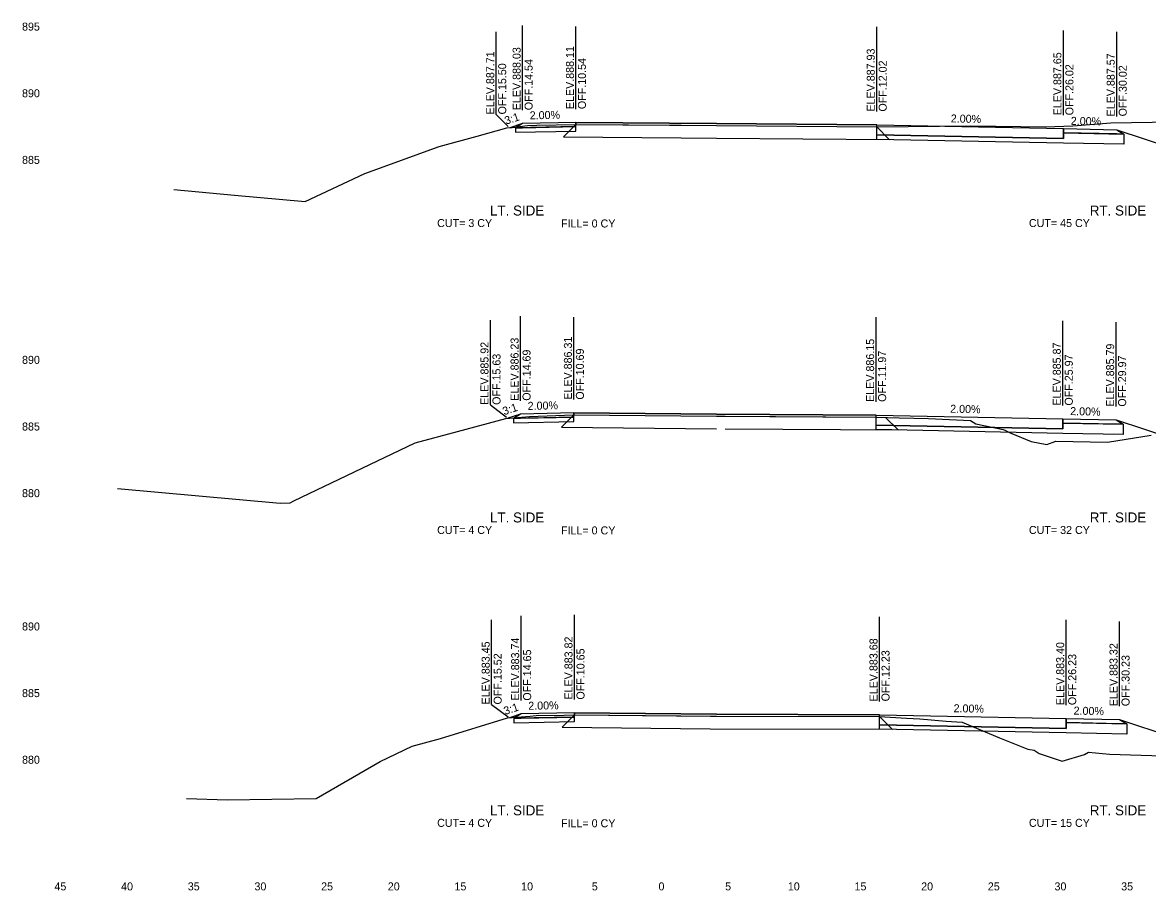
# Model space of a CAD drawing. Extents: x -4 to 359, y 0 to 1436.
# Drawn here: x -3.9 to 80.5, y 1200.5 to 1265.6 of the extents above; entities that cross this region are included whole.
import ezdxf

# ---------------------------------------------------------------- set-up
doc = ezdxf.new("R2010")
doc.units = 0
for name, color, linetype in [('XS-Existing subsurface-pavement', 7, 'Continuous'), ('XS-Existing surface-ground', 7, 'Continuous'), ('XS-Proposed Finish Grade', 7, 'Continuous'), ('XS-Proposed subsurface-aggregate layer 1', 7, 'Continuous'), ('XS-Proposed surface-ground', 7, 'Continuous'), ('XS-Proposed surface-pavement', 7, 'Continuous'), ('XS-Proposed surface-shoulder', 7, 'Continuous'), ('XS-Text-ditch slope', 7, 'Continuous'), ('XS-Text-earthwork labels', 7, 'Continuous'), ('XS-Text-elevation', 7, 'Continuous'), ('XS-Text-offset label', 7, 'Continuous'), ('XS-Text-pavement elevation', 7, 'Continuous'), ('XS-Text-pavement slope', 7, 'Continuous'), ('XS-Text-profile report', 7, 'Continuous'), ('XS-Text-shoulder elevation', 7, 'Continuous'), ('XS-Text-shoulder slope', 7, 'Continuous'), ('XS-Text-tie elevation', 7, 'Continuous'), ('XS-Text-tie offset', 7, 'Continuous')]:
    doc.layers.add(name, color=color, linetype=linetype)

msp = doc.modelspace()

# ---------------------------------------------------------------- linework, layer by layer
at = {"layer": 'XS-Existing subsurface-pavement'}
for p, q in [((37.593, 1257.928), (36.664, 1256.999)), ((60.149, 1257.744), (61.094, 1256.799)), ((36.664, 1256.999), (45.485, 1256.92)), ((45.486, 1256.92), (48.123, 1256.9)), ((48.123, 1256.9), (61.094, 1256.799)), ((37.439, 1236.132), (36.51, 1235.203)), ((36.51, 1235.203), (48.122, 1235.1)), ((60.819, 1235.95), (61.748, 1235.02)), ((48.789, 1235.094), (61.748, 1235.02)), ((37.484, 1213.633), (36.556, 1212.705)), ((60.358, 1213.497), (61.298, 1212.557)), ((36.556, 1212.705), (47.664, 1212.595)), ((47.664, 1212.595), (61.298, 1212.557))]:
    msp.add_line(p, q, dxfattribs=at)
at = {"layer": 'XS-Existing surface-ground'}
for p, q in [((74.849, 1257.813), (77.702, 1258.049)), ((77.702, 1258.049), (82.853, 1258.131)), ((30.192, 1257.053), (32.409, 1257.659)), ((32.409, 1257.659), (32.802, 1257.689)), ((32.802, 1257.689), (33.958, 1257.851)), ((33.958, 1257.851), (34.654, 1257.876)), ((34.654, 1257.876), (37.593, 1257.928)), ((37.593, 1257.928), (45.493, 1257.858)), ((45.493, 1257.858), (48.13, 1257.837)), ((48.13, 1257.837), (60.149, 1257.744)), ((60.149, 1257.744), (67.209, 1257.831)), ((67.209, 1257.831), (72.844, 1257.735)), ((72.844, 1257.735), (74.849, 1257.813)), ((21.756, 1254.233), (27.325, 1256.279)), ((27.325, 1256.279), (30.192, 1257.053)), ((17.28, 1252.137), (21.756, 1254.233)), ((7.427, 1253.042), (11.986, 1252.627)), ((11.986, 1252.627), (17.28, 1252.137)), ((33.843, 1235.987), (34.116, 1236.025)), ((34.116, 1236.025), (36.745, 1236.12)), ((36.745, 1236.12), (37.439, 1236.132)), ((37.439, 1236.132), (48.13, 1236.037)), ((48.13, 1236.037), (48.795, 1236.031)), ((48.795, 1236.031), (60.104, 1235.967)), ((28.713, 1234.885), (32.326, 1235.874)), ((32.326, 1235.874), (33.843, 1235.987)), ((60.104, 1235.967), (61.825, 1235.925)), ((61.825, 1235.925), (64.042, 1235.854)), ((64.042, 1235.854), (67.193, 1235.716)), ((67.193, 1235.716), (67.582, 1235.464)), ((67.582, 1235.464), (69.624, 1235.051)), ((25.543, 1234.029), (28.713, 1234.885)), ((69.624, 1235.051), (69.749, 1234.993)), ((69.749, 1234.993), (70.164, 1234.789)), ((70.164, 1234.789), (71.732, 1234.132)), ((77.453, 1234.084), (80.726, 1234.624)), ((16.432, 1229.69), (25.543, 1234.029)), ((71.732, 1234.132), (72.912, 1233.905)), ((72.912, 1233.905), (73.576, 1234.175)), ((73.576, 1234.175), (77.453, 1234.084)), ((3.218, 1230.621), (15.416, 1229.525)), ((15.416, 1229.525), (16.167, 1229.536)), ((16.167, 1229.536), (16.432, 1229.69)), ((27.433, 1211.847), (32.448, 1213.397)), ((32.448, 1213.397), (34.151, 1213.545)), ((34.151, 1213.545), (34.618, 1213.58)), ((34.618, 1213.58), (36.706, 1213.605)), ((36.706, 1213.605), (37.484, 1213.633)), ((37.484, 1213.633), (47.673, 1213.532)), ((47.673, 1213.532), (48.13, 1213.531)), ((48.13, 1213.531), (60.358, 1213.497)), ((60.358, 1213.497), (62.384, 1213.393)), ((62.384, 1213.393), (63.387, 1213.324)), ((63.387, 1213.324), (65.358, 1213.168)), ((65.358, 1213.168), (66.55, 1213.08)), ((66.55, 1213.08), (69.35, 1211.912)), ((25.316, 1211.275), (27.433, 1211.847)), ((69.35, 1211.912), (71.484, 1211.069)), ((22.912, 1210.131), (25.316, 1211.275)), ((71.484, 1211.069), (71.951, 1210.974)), ((71.951, 1210.974), (72.329, 1210.742)), ((72.329, 1210.742), (74.047, 1210.151)), ((75.721, 1210.667), (76.035, 1210.827)), ((76.035, 1210.827), (77.615, 1210.676)), ((18.117, 1207.346), (22.912, 1210.131)), ((74.047, 1210.151), (75.721, 1210.667)), ((77.615, 1210.676), (92.244, 1210.228)), ((8.376, 1207.348), (11.462, 1207.256)), ((11.462, 1207.256), (18.117, 1207.346))]:
    msp.add_line(p, q, dxfattribs=at)
at = {"layer": 'XS-Proposed Finish Grade'}
for points in [[(37.593, 1258.074), (33.593, 1257.994)], [(37.593, 1258.074), (48.13, 1257.983), (60.149, 1257.889)], [(60.149, 1257.889), (74.149, 1257.609)], [(74.149, 1257.609), (78.149, 1257.529)], [(37.439, 1236.278), (33.439, 1236.198)], [(37.439, 1236.278), (48.13, 1236.183), (60.104, 1236.113)], [(60.104, 1236.113), (74.104, 1235.833)], [(74.104, 1235.833), (78.104, 1235.753)], [(37.484, 1213.779), (33.484, 1213.699)], [(37.484, 1213.779), (48.13, 1213.677), (60.358, 1213.643)], [(60.358, 1213.643), (74.359, 1213.363)], [(74.359, 1213.363), (78.359, 1213.283)]]:
    msp.add_lwpolyline(points, dxfattribs=at)
at = {"layer": 'XS-Proposed subsurface-aggregate layer 1'}
for points in [[(37.593, 1257.761), (33.054, 1257.671)], [(33.054, 1257.671), (33.054, 1257.337)], [(33.054, 1257.337), (37.593, 1257.428)], [(37.593, 1257.428), (37.593, 1257.761)], [(60.149, 1257.139), (74.149, 1256.859)], [(60.149, 1256.806), (60.149, 1257.139)], [(74.149, 1256.859), (74.149, 1257.297)], [(74.149, 1257.297), (78.688, 1257.206)], [(78.688, 1257.206), (78.688, 1256.435)], [(78.688, 1256.435), (74.149, 1256.526), (60.149, 1256.806)], [(37.439, 1235.966), (32.901, 1235.875)], [(32.901, 1235.875), (32.901, 1235.542)], [(32.901, 1235.542), (37.439, 1235.632)], [(37.439, 1235.632), (37.439, 1235.966)], [(60.104, 1235.363), (74.104, 1235.083)], [(60.104, 1235.03), (60.104, 1235.363)], [(74.104, 1235.083), (74.104, 1235.52)], [(74.104, 1235.52), (78.642, 1235.43)], [(78.642, 1235.43), (78.642, 1234.659)], [(78.642, 1234.659), (74.104, 1234.75), (60.104, 1235.03)], [(37.484, 1213.467), (32.946, 1213.376)], [(32.946, 1213.376), (32.946, 1213.043)], [(37.484, 1213.133), (37.484, 1213.467)], [(32.946, 1213.043), (37.484, 1213.133)], [(60.358, 1212.893), (74.359, 1212.613)], [(60.358, 1212.56), (60.358, 1212.893)], [(78.897, 1212.189), (74.359, 1212.28), (60.358, 1212.56)], [(74.359, 1212.613), (74.359, 1213.05)], [(74.359, 1213.05), (78.897, 1212.96)], [(78.897, 1212.96), (78.897, 1212.189)]]:
    msp.add_lwpolyline(points, dxfattribs=at)
at = {"layer": 'XS-Proposed surface-ground'}
msp.add_line((78.104, 1235.753), (85.619, 1233.273), dxfattribs=at)
for points in [[(33.593, 1257.994), (32.629, 1257.676)], [(78.149, 1257.529), (84.149, 1255.549), (88.149, 1255.549), (94.361, 1258.655)], [(33.439, 1236.198), (32.495, 1235.887)], [(33.484, 1213.699), (32.61, 1213.411)], [(78.359, 1213.283), (90.14, 1209.384), (94.14, 1209.384), (95.564, 1210.095)]]:
    msp.add_lwpolyline(points, dxfattribs=at)
at = {"layer": 'XS-Proposed surface-pavement'}
for points in [[(37.593, 1258.074), (37.593, 1257.928)], [(60.149, 1257.889), (48.13, 1257.983), (37.593, 1258.074)], [(37.593, 1257.928), (48.13, 1257.837), (60.149, 1257.744)], [(60.149, 1257.889), (74.149, 1257.609)], [(60.149, 1257.139), (60.149, 1257.889)], [(60.149, 1257.744), (60.149, 1257.889)], [(74.149, 1256.859), (60.149, 1257.139)], [(74.149, 1257.609), (74.149, 1256.859)], [(37.439, 1236.278), (37.439, 1236.132)], [(60.104, 1236.113), (48.13, 1236.183), (37.439, 1236.278)], [(37.439, 1236.132), (48.13, 1236.037), (60.104, 1235.967)], [(60.104, 1236.113), (74.104, 1235.833)], [(60.104, 1235.363), (60.104, 1236.113)], [(60.104, 1235.967), (60.104, 1236.113)], [(74.104, 1235.083), (60.104, 1235.363)], [(74.104, 1235.833), (74.104, 1235.083)], [(37.484, 1213.779), (37.484, 1213.633)], [(60.358, 1213.643), (48.13, 1213.677), (37.484, 1213.779)], [(37.484, 1213.633), (48.13, 1213.531), (60.358, 1213.497)], [(60.358, 1213.643), (74.359, 1213.363)], [(60.358, 1212.893), (60.358, 1213.643)], [(60.358, 1213.497), (60.358, 1213.643)], [(74.359, 1213.363), (74.359, 1212.613)], [(74.359, 1212.613), (60.358, 1212.893)]]:
    msp.add_lwpolyline(points, dxfattribs=at)
at = {"layer": 'XS-Proposed surface-shoulder'}
for points in [[(37.593, 1258.074), (33.593, 1257.994), (33.054, 1257.671)], [(37.593, 1257.761), (37.593, 1258.074)], [(33.054, 1257.671), (33.593, 1257.681), (37.593, 1257.761)], [(74.149, 1257.609), (78.149, 1257.529), (78.688, 1257.206)], [(74.149, 1257.297), (74.149, 1257.609)], [(78.688, 1257.206), (78.149, 1257.217), (74.149, 1257.297)], [(37.439, 1236.278), (33.439, 1236.198), (32.901, 1235.875)], [(37.439, 1235.966), (37.439, 1236.278)], [(32.901, 1235.875), (33.439, 1235.886), (37.439, 1235.966)], [(74.104, 1235.833), (78.104, 1235.753), (78.642, 1235.43)], [(74.104, 1235.52), (74.104, 1235.833)], [(78.642, 1235.43), (78.104, 1235.44), (74.104, 1235.52)], [(37.484, 1213.779), (33.484, 1213.699), (32.946, 1213.376)], [(32.946, 1213.376), (33.484, 1213.387), (37.484, 1213.467)], [(37.484, 1213.467), (37.484, 1213.779)], [(74.359, 1213.363), (78.359, 1213.283), (78.897, 1212.96)], [(74.359, 1213.05), (74.359, 1213.363)], [(78.897, 1212.96), (78.359, 1212.97), (74.359, 1213.05)]]:
    msp.add_lwpolyline(points, dxfattribs=at)
at = {"layer": 'XS-Text-tie offset'}
for p, q in [((31.614, 1258.676), (31.614, 1264.876)), ((33.593, 1258.994), (33.593, 1265.344)), ((37.593, 1259.074), (37.593, 1265.274)), ((60.149, 1258.889), (60.149, 1265.239)), ((74.149, 1258.609), (74.149, 1264.961)), ((78.149, 1258.529), (78.149, 1264.879)), ((31.614, 1258.676), (32.506, 1257.775)), ((31.184, 1236.887), (31.184, 1243.237)), ((33.439, 1237.198), (33.439, 1243.548)), ((37.439, 1237.278), (37.439, 1243.478)), ((60.104, 1237.113), (60.104, 1243.465)), ((74.104, 1236.833), (74.104, 1243.183)), ((78.104, 1236.753), (78.104, 1243.103)), ((31.184, 1236.887), (32.383, 1235.972)), ((33.484, 1214.699), (33.484, 1221.049)), ((37.484, 1214.779), (37.484, 1221.129)), ((60.358, 1214.643), (60.358, 1220.993)), ((31.272, 1214.411), (31.272, 1220.763)), ((74.359, 1214.363), (74.359, 1220.761)), ((78.359, 1214.283), (78.359, 1220.633)), ((31.272, 1214.411), (32.508, 1213.487))]:
    msp.add_line(p, q, dxfattribs=at)

# ---------------------------------------------------------------- texts
at = {"layer": 'XS-Text-ditch slope'}
for p in [(32.352, 1257.9), (32.208, 1236.108), (32.288, 1213.62)]:
    msp.add_text('3:1', height=0.6, rotation=18.26289, dxfattribs=at).set_placement(p)
at = {"layer": 'XS-Text-earthwork labels'}
for s, height, p in [('LT. SIDE', 0.75, (31.148, 1251.092)), ('RT. SIDE', 0.75, (76.127, 1251.092)), (' CUT= 3 CY           ', 0.6, (26.96, 1250.227)), ('FILL= 0 CY           ', 0.6, (36.472, 1250.196)), (' CUT= 45 CY           ', 0.6, (71.341, 1250.227)), ('LT. SIDE', 0.75, (31.148, 1228.067)), ('RT. SIDE', 0.75, (76.127, 1228.067)), (' CUT= 4 CY           ', 0.6, (26.96, 1227.202)), ('FILL= 0 CY           ', 0.6, (36.472, 1227.17)), (' CUT= 32 CY           ', 0.6, (71.341, 1227.202)), ('LT. SIDE', 0.75, (31.148, 1206.095)), ('RT. SIDE', 0.75, (76.127, 1206.095)), (' CUT= 4 CY           ', 0.6, (26.96, 1205.23)), ('FILL= 0 CY           ', 0.6, (36.472, 1205.199)), (' CUT= 15 CY           ', 0.6, (71.341, 1205.23))]:
    msp.add_text(s, height=height, dxfattribs=at).set_placement(p)
at = {"layer": 'XS-Text-elevation'}
for s, p in [('           895           ', (-6.4, 1264.964)), ('           890           ', (-6.4, 1259.964)), ('           885           ', (-6.4, 1254.964)), ('           890           ', (-6.4, 1239.964)), ('           885           ', (-6.4, 1234.964)), ('           880           ', (-6.4, 1229.964)), ('           890           ', (-6.4, 1219.964)), ('           885           ', (-6.4, 1214.964)), ('           880           ', (-6.4, 1209.964))]:
    msp.add_text(s, height=0.6, dxfattribs=at).set_placement(p)
at = {"layer": 'XS-Text-offset label'}
for s, p in [('           45           ', (-3.97, 1200.464)), ('           40           ', (1.03, 1200.464)), ('           35           ', (6.03, 1200.464)), ('           30           ', (11.03, 1200.464)), ('           25           ', (16.03, 1200.464)), ('           20           ', (21.03, 1200.464)), ('           15           ', (26.03, 1200.464)), ('           10           ', (31.03, 1200.464)), ('           5           ', (36.33, 1200.464)), ('           0           ', (41.33, 1200.464)), ('           0           ', (41.33, 1200.464)), ('           5           ', (46.33, 1200.464)), ('           10           ', (51.03, 1200.464)), ('           15           ', (56.03, 1200.464)), ('           20           ', (61.03, 1200.464)), ('           25           ', (66.03, 1200.464)), ('           30           ', (71.03, 1200.464)), ('           35           ', (76.03, 1200.464))]:
    msp.add_text(s, height=0.6, dxfattribs=at).set_placement(p)
at = {"layer": 'XS-Text-pavement elevation'}
for s, p in [('ELEV.888.03', (33.443, 1258.994)), ('ELEV.888.11', (37.443, 1259.074)), ('ELEV.887.93', (59.999, 1258.889)), ('ELEV.887.65', (73.999, 1258.609)), ('OFF.14.54', (34.343, 1258.994)), ('OFF.10.54', (38.343, 1259.074)), ('OFF.12.02', (60.899, 1258.889)), ('OFF.26.02', (74.899, 1258.609)), ('ELEV.886.31', (37.289, 1237.278)), ('ELEV.886.23', (33.289, 1237.198)), ('OFF.10.69', (38.189, 1237.278)), ('ELEV.886.15', (59.954, 1237.113)), ('ELEV.885.87', (73.954, 1236.833)), ('OFF.14.69', (34.189, 1237.198)), ('OFF.11.97', (60.854, 1237.113)), ('OFF.25.97', (74.854, 1236.833)), ('ELEV.883.74', (33.334, 1214.699)), ('ELEV.883.82', (37.334, 1214.779)), ('ELEV.883.68', (60.208, 1214.643)), ('OFF.14.65', (34.234, 1214.699)), ('OFF.10.65', (38.234, 1214.779)), ('OFF.12.23', (61.108, 1214.643)), ('ELEV.883.40', (74.209, 1214.363)), ('OFF.26.23', (75.109, 1214.363))]:
    msp.add_text(s, height=0.6, rotation=90, dxfattribs=at).set_placement(p)
at = {"layer": 'XS-Text-pavement slope'}
for p in [(65.699, 1258.078), (65.654, 1236.302), (65.908, 1213.832)]:
    msp.add_text('2.00%', height=0.6, rotation=358.85424, dxfattribs=at).set_placement(p)
at = {"layer": 'XS-Text-profile report'}
for s, p in [('Shldr_Surf_Asph_T1', (33.578, 1257.993)), ('Pvmt_Surf_Asph_T2_L', (37.577, 1258.073)), ('Pvmt_Surf_Asph_T1', (48.116, 1257.982)), ('Fill_Slope_2_B', (32.618, 1257.675)), ('Shldr_Surf_Asph_B2', (33.039, 1257.67)), ('Agg_Layer_1_B1', (33.043, 1257.336)), ('Shldr_Surf_Asph_B1', (33.578, 1257.681)), ('Shldr_Surf_Asph_B12', (37.577, 1257.761)), ('Pvmt_Surf_Asph_T_L', (37.578, 1257.927)), ('Agg_Layer_1_B', (37.582, 1257.427)), ('Pvmt_Surf_Asph_T', (48.117, 1257.836)), ('Pvmt_Surf_Asph_T1_R', (60.134, 1257.889)), ('Pvmt_Surf_Asph_T_R', (60.134, 1257.743)), ('Pvmt_Surf_Conc_B_R', (60.134, 1257.139)), ('Pvmt_Surf_Conc_T1_R', (74.134, 1257.609)), ('Shldr_Surf_Asph_B13', (74.134, 1257.296)), ('Shldr_Surf_Asph_T11', (78.134, 1257.529)), ('Shldr_Surf_Asph_B11', (78.134, 1257.216)), ('Shldr_Surf_Asph_B21', (78.673, 1257.205)), ('Agg_Layer_1_B2', (60.138, 1256.805)), ('Pvmt_Surf_Conc_B1_R', (74.134, 1256.859)), ('Agg_Layer_1_B11', (74.137, 1256.525)), ('Agg_Layer_1_B12', (78.676, 1256.434)), ('Shldr_Surf_Asph_T1', (33.425, 1236.197)), ('Pvmt_Surf_Asph_T2_L', (37.424, 1236.277)), ('Pvmt_Surf_Asph_T_L', (37.425, 1236.132)), ('Pvmt_Surf_Asph_T1', (48.116, 1236.182)), ('Pvmt_Surf_Asph_T', (48.117, 1236.037)), ('Pvmt_Surf_Asph_T1_R', (60.088, 1236.112)), ('Fill_Slope_2_B', (32.484, 1235.886)), ('Shldr_Surf_Asph_B2', (32.886, 1235.874)), ('Agg_Layer_1_B1', (32.889, 1235.541)), ('Shldr_Surf_Asph_B1', (33.425, 1235.885)), ('Shldr_Surf_Asph_B12', (37.424, 1235.965)), ('Agg_Layer_1_B', (37.429, 1235.632)), ('Pvmt_Surf_Asph_T_R', (60.089, 1235.966)), ('Pvmt_Surf_Conc_B_R', (60.089, 1235.362)), ('Pvmt_Surf_Conc_T1_R', (74.088, 1235.832)), ('Shldr_Surf_Asph_B13', (74.088, 1235.52)), ('Shldr_Surf_Asph_T11', (78.088, 1235.752)), ('Shldr_Surf_Asph_B11', (78.088, 1235.44)), ('Shldr_Surf_Asph_B21', (78.627, 1235.429)), ('Agg_Layer_1_B2', (60.092, 1235.029)), ('Pvmt_Surf_Conc_B1_R', (74.088, 1235.082)), ('Agg_Layer_1_B11', (74.092, 1234.749)), ('Agg_Layer_1_B12', (78.63, 1234.658)), ('Fill_Slope_2_B', (32.599, 1213.41)), ('Shldr_Surf_Asph_B2', (32.931, 1213.375)), ('Shldr_Surf_Asph_T1', (33.47, 1213.698)), ('Shldr_Surf_Asph_B1', (33.47, 1213.386)), ('Pvmt_Surf_Asph_T2_L', (37.469, 1213.778)), ('Shldr_Surf_Asph_B12', (37.469, 1213.466)), ('Pvmt_Surf_Asph_T_L', (37.47, 1213.632)), ('Pvmt_Surf_Asph_T1', (48.116, 1213.676)), ('Pvmt_Surf_Asph_T', (48.117, 1213.53)), ('Pvmt_Surf_Asph_T1_R', (60.343, 1213.642)), ('Pvmt_Surf_Asph_T_R', (60.343, 1213.496)), ('Pvmt_Surf_Conc_T1_R', (74.343, 1213.362)), ('Shldr_Surf_Asph_T11', (78.343, 1213.282)), ('Agg_Layer_1_B1', (32.934, 1213.042)), ('Agg_Layer_1_B', (37.474, 1213.132)), ('Pvmt_Surf_Conc_B_R', (60.343, 1212.892)), ('Agg_Layer_1_B2', (60.347, 1212.559)), ('Shldr_Surf_Asph_B13', (74.343, 1213.049)), ('Pvmt_Surf_Conc_B1_R', (74.343, 1212.612)), ('Shldr_Surf_Asph_B11', (78.343, 1212.969)), ('Shldr_Surf_Asph_B21', (78.882, 1212.959)), ('Agg_Layer_1_B11', (74.347, 1212.279)), ('Agg_Layer_1_B12', (78.885, 1212.188))]:
    msp.add_text(s, height=0.00167, dxfattribs=at).set_placement(p)
at = {"layer": 'XS-Text-shoulder elevation'}
for s, p in [('ELEV.887.57', (77.999, 1258.529)), ('OFF.30.02', (78.899, 1258.529)), ('ELEV.885.79', (77.954, 1236.753)), ('OFF.29.97', (78.854, 1236.753)), ('ELEV.883.32', (78.209, 1214.283)), ('OFF.30.23', (79.109, 1214.283))]:
    msp.add_text(s, height=0.6, rotation=90, dxfattribs=at).set_placement(p)
at = {"layer": 'XS-Text-shoulder slope'}
for rotation, p in [(1.14576, (34.131, 1258.305)), (358.85424, (74.699, 1257.898)), (1.14576, (33.977, 1236.509)), (358.85424, (74.654, 1236.122)), (1.14576, (34.022, 1214.01)), (358.85424, (74.909, 1213.652))]:
    msp.add_text('2.00%', height=0.6, rotation=rotation, dxfattribs=at).set_placement(p)
at = {"layer": 'XS-Text-tie elevation'}
for s, p in [('ELEV.887.71', (31.464, 1258.676)), ('OFF.15.50', (32.364, 1258.676)), ('ELEV.885.92', (31.034, 1236.887)), ('OFF.15.63', (31.934, 1236.887)), ('ELEV.883.45', (31.122, 1214.411)), ('OFF.15.52', (32.022, 1214.411))]:
    msp.add_text(s, height=0.6, rotation=90, dxfattribs=at).set_placement(p)

doc.saveas('drawing.dxf')
